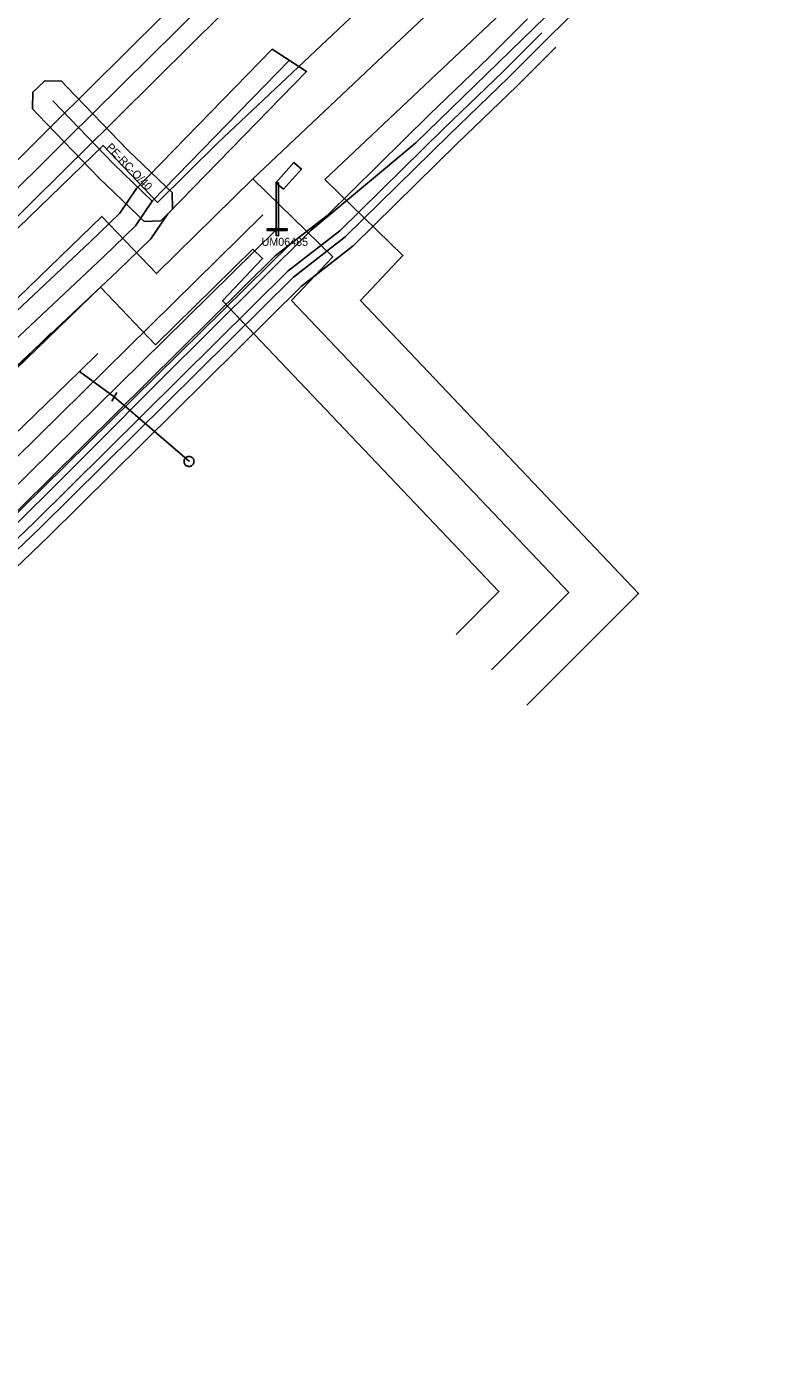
# Model space of a CAD drawing. Extents: x -762993 to -761845, y -975230 to -974501.
# Drawn here: x -762204.7 to -762166.8, y -974983.8 to -974917.1 of the extents above; entities that cross this region are included whole.
import ezdxf

# ---------------------------------------------------------------- set-up
doc = ezdxf.new("R2010")
doc.units = 0
for name, color, linetype in [('IS_CEZ-D_el vedeni NN podzem', 7, 'Continuous'), ('IS_CEZ-D_el vedeni VN podzem', 7, 'Continuous'), ('IS_CEZ-D_el vedeni VN podzem soubeh investice', 7, 'Continuous'), ('IS_CEZ-D_OP', 7, 'Continuous'), ('IS_CEZ-T_parovod', 7, 'Continuous'), ('IS_CEZ-T_parovod OP', 7, 'Continuous'), ('IS_DPmUL_OP', 7, 'Continuous'), ('IS_DPmUL_VO lampy', 7, 'Continuous'), ('IS_DPmUL_VO lampy anotace', 7, 'Continuous'), ('IS_DPmUL_VO vedeni podzem', 7, 'Continuous'), ('IS_GASNET_plyn NTL anotace', 7, 'Continuous'), ('IS_GASNET_plyn NTL pripojky', 7, 'Continuous'), ('IS_GASNET_plyn NTL rad', 7, 'Continuous'), ('IS_GASNET_plyn OP', 7, 'Continuous'), ('IS_SCVK_kanalizace jednotna', 7, 'Continuous'), ('IS_SCVK_vodovod pripojky', 7, 'Continuous'), ('IS_SCVK_vodovod privadec', 7, 'Continuous'), ('IS_SCVK_vodovod znaky', 7, 'Continuous'), ('IS_TPS_podzem metalika', 7, 'Continuous')]:
    doc.layers.add(name, color=color, linetype=linetype)

msp = doc.modelspace()

# ---------------------------------------------------------------- linework, layer by layer
at = {"layer": 'IS_CEZ-D_el vedeni NN podzem'}
msp.add_lwpolyline([(-762247.847, -974984.536), (-762246.114, -974982.893), (-762246.05, -974980.697), (-762253.7, -974972.107), (-762252.057, -974970.493), (-762250.973, -974969.428), (-762239.791, -974958.41), (-762235.916, -974954.845), (-762234.541, -974953.31), (-762221.186, -974940.477), (-762220.991, -974940.306), (-762216.22, -974936.128), (-762203.456, -974923.483), (-762203.186, -974923.213), (-762202.673, -974922.708), (-762197.126, -974917.211), (-762182.367, -974902.622)], dxfattribs=at)
at = {"layer": 'IS_CEZ-D_el vedeni VN podzem'}
msp.add_lwpolyline([(-762178.94, -974917.38), (-762180.88, -974919.33), (-762183.85, -974922.18), (-762189.02, -974927.27), (-762191.6, -974929.28), (-762204.29, -974941.85), (-762215.61, -974952.68), (-762222.04, -974959.06), (-762225.71, -974962.96), (-762226.91, -974964.67), (-762236.89, -974974.42), (-762240.73, -974978.21), (-762245.09, -974982.81)], dxfattribs=at)
at = {"layer": 'IS_CEZ-D_el vedeni VN podzem soubeh investice'}
msp.add_lwpolyline([(-762246.655, -974985.018), (-762244.801, -974983.086), (-762240.444, -974978.49), (-762236.61, -974974.705), (-762226.604, -974964.93), (-762225.399, -974963.213), (-762221.753, -974959.339), (-762215.331, -974952.967), (-762204.011, -974942.137), (-762191.335, -974929.581), (-762188.756, -974927.571), (-762183.571, -974922.467), (-762180.6, -974919.615), (-762178.658, -974917.664), (-762169.2, -974908.366)], dxfattribs=at)
at = {"layer": 'IS_CEZ-D_OP'}
for points in [[(-762235.261, -974952.615), (-762221.862, -974939.74), (-762221.65, -974939.554), (-762216.902, -974935.396), (-762204.161, -974922.774), (-762203.89, -974922.503), (-762203.376, -974921.997), (-762197.829, -974916.5), (-762183.107, -974901.948), (-762182.738, -974901.004), (-762180.901, -974896.322), (-762175.443, -974882.405), (-762170.837, -974870.904), (-762171.08, -974867.387), (-762172.169, -974851.621), (-762173.361, -974831.196), (-762173.4, -974830.555), (-762173.438, -974829.89), (-762173.725, -974824.972), (-762174.311, -974821.59), (-762174.662, -974815.176), (-762174.624, -974813.433), (-762174.492, -974807.288)], [(-762252.034, -974971.872), (-762251.356, -974971.206), (-762250.272, -974970.141), (-762239.101, -974959.134), (-762235.203, -974955.548), (-762233.821, -974954.005), (-762220.51, -974941.214), (-762220.332, -974941.058), (-762215.538, -974936.86), (-762202.751, -974924.192), (-762202.482, -974923.923), (-762201.97, -974923.419), (-762196.423, -974917.922), (-762181.665, -974903.334)], [(-762179.649, -974916.675), (-762181.581, -974918.616), (-762184.547, -974921.463), (-762189.68, -974926.517), (-762192.261, -974928.528), (-762204.988, -974941.133), (-762212.335, -974948.163)], [(-762178.231, -974918.085), (-762180.179, -974920.044), (-762183.153, -974922.897), (-762188.36, -974928.023), (-762190.939, -974930.032), (-762203.592, -974942.567), (-762210.996, -974949.649)]]:
    msp.add_lwpolyline(points, dxfattribs=at)
at = {"layer": 'IS_CEZ-T_parovod'}
for points in [[(-762193.38, -974924.68), (-762168.49, -974901.16), (-762168.49, -974901.16), (-762168.49, -974901.16), (-762168.49, -974901.16)], [(-762252.5, -975008.59), (-762252.58, -975007.19), (-762253.19, -974987.18), (-762253.2, -974985.67), (-762257.54, -974981.54), (-762246.7, -974971.01), (-762237.24, -974961.81), (-762238.76, -974960.21), (-762237.06, -974958.42), (-762235.35, -974960.05), (-762220.52, -974945.72), (-762219.73, -974944.77), (-762200.92, -974926.55), (-762198.18, -974929.41), (-762193.38, -974924.68)], [(-762193.38, -974924.68), (-762189.38, -974928.58), (-762191.44, -974930.76), (-762177.59, -974945.35), (-762181.45, -974949.21)]]:
    msp.add_lwpolyline(points, dxfattribs=at)
at = {"layer": 'IS_CEZ-T_parovod OP'}
for p, q in [((-762195.116, -974922.881), (-762170.207, -974899.343)), ((-762189.77, -974924.708), (-762166.773, -974902.977))]:
    msp.add_line(p, q, dxfattribs=at)
for points in [[(-762254.996, -975008.733), (-762255.078, -975007.299), (-762255.69, -974987.226), (-762255.693, -974986.749), (-762261.147, -974981.559), (-762248.442, -974969.217), (-762240.754, -974961.74), (-762242.208, -974960.21), (-762237.148, -974954.882), (-762235.362, -974956.585), (-762222.355, -974944.017), (-762221.566, -974943.068), (-762200.854, -974923.005), (-762198.129, -974925.85), (-762195.116, -974922.881)], [(-762189.77, -974924.708), (-762185.873, -974928.508), (-762187.997, -974930.756), (-762174.1, -974945.395), (-762179.682, -974950.978)], [(-762250.004, -975008.447), (-762250.082, -975007.081), (-762250.69, -974987.134), (-762250.707, -974984.591), (-762253.933, -974981.521), (-762244.958, -974972.803), (-762235.373, -974963.482), (-762235.338, -974963.515), (-762218.685, -974947.423), (-762217.894, -974946.472), (-762200.986, -974930.095), (-762198.231, -974932.97), (-762193.371, -974928.181)], [(-762193.371, -974928.181), (-762192.887, -974928.652), (-762194.883, -974930.764), (-762181.08, -974945.305), (-762183.218, -974947.442)]]:
    msp.add_lwpolyline(points, dxfattribs=at)
at = {"layer": 'IS_DPmUL_OP'}
for points in [[(-762208.624, -974941.986), (-762192.88, -974926.476)], [(-762207.22, -974943.41), (-762191.476, -974927.9)]]:
    msp.add_lwpolyline(points, dxfattribs=at)
at = {"layer": 'IS_DPmUL_VO lampy'}
for points in [[(-762191.318, -974923.858), (-762190.948, -974924.188), (-762191.848, -974925.188), (-762192.228, -974924.868)], [(-762192.208, -974924.868), (-762192.088, -974924.878), (-762192.088, -974927.518), (-762192.208, -974927.508)], [(-762192.658, -974927.168), (-762191.658, -974927.168), (-762191.658, -974927.258), (-762192.648, -974927.258)]]:
    msp.add_lwpolyline(points, close=True, dxfattribs=at)
at = {"layer": 'IS_DPmUL_VO vedeni podzem'}
msp.add_lwpolyline([(-762207.922, -974942.698), (-762192.178, -974927.188)], dxfattribs=at)
at = {"layer": 'IS_GASNET_plyn NTL pripojky'}
msp.add_lwpolyline([(-762198.4, -974925.79), (-762200.34, -974923.93), (-762203.37, -974920.78)], dxfattribs=at)
at = {"layer": 'IS_GASNET_plyn NTL rad'}
msp.add_lwpolyline([(-762254.38, -974980.34), (-762254.3, -974980.18), (-762254.49, -974979.97), (-762249.33, -974975.11), (-762246.79, -974972.7), (-762240.45, -974966.56), (-762232.17, -974958.5), (-762223.94, -974950.53), (-762218.08, -974944.94), (-762212.07, -974939.13), (-762200.83, -974928.57), (-762199.24, -974927.03), (-762198.4, -974925.79), (-762191.542, -974918.748)], dxfattribs=at)
at = {"layer": 'IS_GASNET_plyn OP'}
msp.add_lwpolyline([(-762212.76, -974938.406), (-762201.52, -974927.846), (-762200.01, -974926.384), (-762199.178, -974925.156), (-762192.399, -974918.195), (-762190.686, -974919.302), (-762197.622, -974926.424), (-762198.47, -974927.676), (-762200.14, -974929.294), (-762211.38, -974939.854)], dxfattribs=at)
msp.add_lwpolyline([(-762198.793, -974926.799), (-762199.092, -974926.512), (-762201.047, -974924.638), (-762204.091, -974921.473), (-762204.378, -974921.175), (-762204.362, -974920.346), (-762204.063, -974920.059), (-762203.765, -974919.772), (-762202.936, -974919.788), (-762202.649, -974920.087), (-762199.633, -974923.222), (-762197.708, -974925.068), (-762197.409, -974925.355), (-762197.391, -974926.183), (-762197.678, -974926.482), (-762197.965, -974926.781)], close=True, dxfattribs=at)
at = {"layer": 'IS_SCVK_kanalizace jednotna'}
msp.add_lwpolyline([(-762237.305, -974965.834), (-762203.442, -974932.379)], dxfattribs=at)
at = {"layer": 'IS_SCVK_vodovod pripojky'}
for points in [[(-762202.03, -974934.3), (-762200.291, -974935.569)], [(-762200.291, -974935.569), (-762196.544, -974938.798)]]:
    msp.add_lwpolyline(points, dxfattribs=at)
at = {"layer": 'IS_SCVK_vodovod privadec'}
msp.add_lwpolyline([(-762201.113, -974933.408), (-762202.03, -974934.3), (-762216.385, -974948.217)], dxfattribs=at)
at = {"layer": 'IS_SCVK_vodovod znaky'}
for points in [[(-762200.166, -974935.352), (-762200.416, -974935.785)], [(-762196.807, -974938.767), (-762196.81, -974938.793)], [(-762196.807, -974938.767), (-762196.81, -974938.793)], [(-762196.81, -974938.793), (-762196.809, -974938.82)], [(-762196.81, -974938.793), (-762196.809, -974938.82)], [(-762196.809, -974938.82), (-762196.806, -974938.846)], [(-762196.809, -974938.82), (-762196.806, -974938.846)], [(-762196.803, -974938.741), (-762196.807, -974938.767)], [(-762196.803, -974938.741), (-762196.807, -974938.767)], [(-762196.806, -974938.846), (-762196.8, -974938.871)], [(-762196.806, -974938.846), (-762196.8, -974938.871)], [(-762196.797, -974938.716), (-762196.803, -974938.741)], [(-762196.797, -974938.716), (-762196.803, -974938.741)], [(-762196.8, -974938.871), (-762196.79, -974938.895)], [(-762196.8, -974938.871), (-762196.79, -974938.895)], [(-762196.787, -974938.692), (-762196.797, -974938.716)], [(-762196.787, -974938.692), (-762196.797, -974938.716)], [(-762196.79, -974938.895), (-762196.78, -974938.919)], [(-762196.79, -974938.895), (-762196.78, -974938.919)], [(-762196.774, -974938.669), (-762196.787, -974938.692)], [(-762196.774, -974938.669), (-762196.787, -974938.692)], [(-762196.78, -974938.919), (-762196.765, -974938.941)], [(-762196.78, -974938.919), (-762196.765, -974938.941)], [(-762196.76, -974938.647), (-762196.774, -974938.669)], [(-762196.76, -974938.647), (-762196.774, -974938.669)], [(-762196.765, -974938.941), (-762196.748, -974938.961)], [(-762196.765, -974938.941), (-762196.748, -974938.961)], [(-762196.743, -974938.627), (-762196.76, -974938.647)], [(-762196.743, -974938.627), (-762196.76, -974938.647)], [(-762196.748, -974938.961), (-762196.731, -974938.98)], [(-762196.748, -974938.961), (-762196.731, -974938.98)], [(-762196.724, -974938.61), (-762196.743, -974938.627)], [(-762196.724, -974938.61), (-762196.743, -974938.627)], [(-762196.731, -974938.98), (-762196.711, -974938.997)], [(-762196.731, -974938.98), (-762196.711, -974938.997)], [(-762196.703, -974938.593), (-762196.724, -974938.61)], [(-762196.703, -974938.593), (-762196.724, -974938.61)], [(-762196.711, -974938.997), (-762196.689, -974939.012)], [(-762196.711, -974938.997), (-762196.689, -974939.012)], [(-762196.681, -974938.579), (-762196.703, -974938.593)], [(-762196.681, -974938.579), (-762196.703, -974938.593)], [(-762196.689, -974939.012), (-762196.666, -974939.025)], [(-762196.689, -974939.012), (-762196.666, -974939.025)], [(-762196.658, -974938.568), (-762196.681, -974938.579)], [(-762196.658, -974938.568), (-762196.681, -974938.579)], [(-762196.666, -974939.025), (-762196.642, -974939.034)], [(-762196.666, -974939.025), (-762196.642, -974939.034)], [(-762196.633, -974938.559), (-762196.658, -974938.568)], [(-762196.633, -974938.559), (-762196.658, -974938.568)], [(-762196.642, -974939.034), (-762196.617, -974939.042)], [(-762196.642, -974939.034), (-762196.617, -974939.042)], [(-762196.608, -974938.552), (-762196.633, -974938.559)], [(-762196.608, -974938.552), (-762196.633, -974938.559)], [(-762196.617, -974939.042), (-762196.591, -974939.046)], [(-762196.617, -974939.042), (-762196.591, -974939.046)], [(-762196.582, -974938.549), (-762196.608, -974938.552)], [(-762196.582, -974938.549), (-762196.608, -974938.552)], [(-762196.591, -974939.046), (-762196.564, -974939.048)], [(-762196.591, -974939.046), (-762196.564, -974939.048)], [(-762196.556, -974938.548), (-762196.582, -974938.549)], [(-762196.556, -974938.548), (-762196.582, -974938.549)], [(-762196.564, -974939.048), (-762196.539, -974939.047)], [(-762196.564, -974939.048), (-762196.539, -974939.047)], [(-762196.53, -974938.55), (-762196.556, -974938.548)], [(-762196.53, -974938.55), (-762196.556, -974938.548)], [(-762196.539, -974939.047), (-762196.513, -974939.044)], [(-762196.539, -974939.047), (-762196.513, -974939.044)], [(-762196.503, -974938.554), (-762196.53, -974938.55)], [(-762196.503, -974938.554), (-762196.53, -974938.55)], [(-762196.513, -974939.044), (-762196.487, -974939.037)], [(-762196.513, -974939.044), (-762196.487, -974939.037)], [(-762196.478, -974938.562), (-762196.503, -974938.554)], [(-762196.478, -974938.562), (-762196.503, -974938.554)], [(-762196.487, -974939.037), (-762196.463, -974939.028)], [(-762196.487, -974939.037), (-762196.463, -974939.028)], [(-762196.454, -974938.572), (-762196.478, -974938.562)], [(-762196.454, -974938.572), (-762196.478, -974938.562)], [(-762196.463, -974939.028), (-762196.439, -974939.017)], [(-762196.463, -974939.028), (-762196.439, -974939.017)], [(-762196.431, -974938.584), (-762196.454, -974938.572)], [(-762196.431, -974938.584), (-762196.454, -974938.572)], [(-762196.439, -974939.017), (-762196.417, -974939.003)], [(-762196.439, -974939.017), (-762196.417, -974939.003)], [(-762196.41, -974938.599), (-762196.431, -974938.584)], [(-762196.41, -974938.599), (-762196.431, -974938.584)], [(-762196.417, -974939.003), (-762196.397, -974938.987)], [(-762196.417, -974939.003), (-762196.397, -974938.987)], [(-762196.389, -974938.616), (-762196.41, -974938.599)], [(-762196.389, -974938.616), (-762196.41, -974938.599)], [(-762196.397, -974938.987), (-762196.378, -974938.969)], [(-762196.397, -974938.987), (-762196.378, -974938.969)], [(-762196.371, -974938.635), (-762196.389, -974938.616)], [(-762196.371, -974938.635), (-762196.389, -974938.616)], [(-762196.378, -974938.969), (-762196.361, -974938.949)], [(-762196.378, -974938.969), (-762196.361, -974938.949)], [(-762196.355, -974938.655), (-762196.371, -974938.635)], [(-762196.355, -974938.655), (-762196.371, -974938.635)], [(-762196.361, -974938.949), (-762196.346, -974938.927)], [(-762196.361, -974938.949), (-762196.346, -974938.927)], [(-762196.341, -974938.677), (-762196.355, -974938.655)], [(-762196.341, -974938.677), (-762196.355, -974938.655)], [(-762196.346, -974938.927), (-762196.334, -974938.904)], [(-762196.346, -974938.927), (-762196.334, -974938.904)], [(-762196.329, -974938.701), (-762196.341, -974938.677)], [(-762196.329, -974938.701), (-762196.341, -974938.677)], [(-762196.334, -974938.904), (-762196.324, -974938.88)], [(-762196.334, -974938.904), (-762196.324, -974938.88)], [(-762196.321, -974938.726), (-762196.329, -974938.701)], [(-762196.321, -974938.726), (-762196.329, -974938.701)], [(-762196.324, -974938.88), (-762196.317, -974938.855)], [(-762196.324, -974938.88), (-762196.317, -974938.855)], [(-762196.314, -974938.751), (-762196.321, -974938.726)], [(-762196.314, -974938.751), (-762196.321, -974938.726)], [(-762196.317, -974938.855), (-762196.312, -974938.829)], [(-762196.317, -974938.855), (-762196.312, -974938.829)], [(-762196.312, -974938.777), (-762196.314, -974938.751)], [(-762196.312, -974938.777), (-762196.314, -974938.751)], [(-762196.311, -974938.803), (-762196.312, -974938.777)], [(-762196.311, -974938.803), (-762196.312, -974938.777)], [(-762196.312, -974938.829), (-762196.311, -974938.803)], [(-762196.312, -974938.829), (-762196.311, -974938.803)]]:
    msp.add_lwpolyline(points, dxfattribs=at)
at = {"layer": 'IS_TPS_podzem metalika'}
msp.add_lwpolyline([(-762172.29, -974910.28), (-762185.23, -974922.87), (-762190.46, -974927.24), (-762198, -974934.74), (-762201.39, -974938.15), (-762206.9, -974943.61), (-762214.43, -974950.91), (-762220.21, -974956.46), (-762222.55, -974958.76), (-762223.79, -974960.27), (-762224.33, -974962.55), (-762233.162, -974970.759), (-762240.486, -974977.956), (-762246.238, -974984.004)], dxfattribs=at)

# ---------------------------------------------------------------- texts
at = {"layer": 'IS_DPmUL_VO lampy anotace'}
msp.add_text('UM06485', height=0.4, dxfattribs=at).set_placement((-762192.934, -974928.021))
at = {"layer": 'IS_GASNET_plyn NTL anotace'}
msp.add_text('PE-RC-O/40', height=0.4, rotation=313.8876, dxfattribs=at).set_placement((-762200.723, -974923.123))

doc.saveas('drawing.dxf')
